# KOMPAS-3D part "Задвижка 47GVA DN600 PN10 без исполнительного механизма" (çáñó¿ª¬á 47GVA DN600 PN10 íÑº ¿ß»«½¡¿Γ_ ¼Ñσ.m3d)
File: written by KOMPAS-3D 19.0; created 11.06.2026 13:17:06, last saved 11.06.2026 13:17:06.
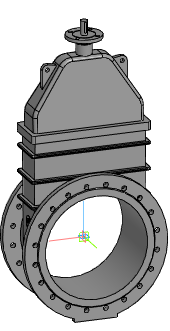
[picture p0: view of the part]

Document properties: Автор: Евгений; Полное имя файла: Z:\3.Личные\kachalov\001_3d для проектировщиков\2.2 Тип 47GVA, 47GVA.Z\_stp\_stp_Задвижка 47GVA DN40-DN1000 без исп.мех\Задвижка 47GVA DN600 PN10 без исполнит_ мех.m3d

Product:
- Part/product: Задвижка 47GVA DN600 PN10 без исполнительного механизма

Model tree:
1. Операция без истории:1  (labels: Задвижка 47GVA DN600 PN10 без исполнительного механизма)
